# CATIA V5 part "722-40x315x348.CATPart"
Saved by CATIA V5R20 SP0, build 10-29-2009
Part number: 722-40x315x348
Definition: NONE
Nomenclature: 722-40x315x348
Source: Unknown
Description: 722-40x315x348
Bounding box of the stored display mesh (mm): x -20 to 20, y -20 to 20, z -300 to 48
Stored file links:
  C:\Users\Utente\Desktop\IO LAVORO\3D X SITO CF\X SITO\722\722-40x315x348.CATPart
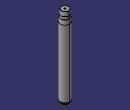
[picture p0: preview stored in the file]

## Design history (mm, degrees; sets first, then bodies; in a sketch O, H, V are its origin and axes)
Body1 "722-40x315x348" (main body)
  Solid1: solid without history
